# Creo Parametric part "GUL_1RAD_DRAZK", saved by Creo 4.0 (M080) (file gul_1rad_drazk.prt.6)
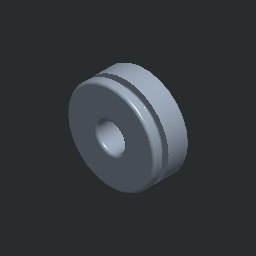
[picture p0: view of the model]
Units: millimeter Kilogram Sec (mmKs); MM, KILOGRAM, SECS
Materials in the file: OCEL_N

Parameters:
  MFG_WP_MATERIAL = "RO5_5"
  NAZOV = "GUL_1RAD_DRAZK"
  PTC_MATERIAL_NAME = "OCEL_N"

Other parameters: HMOTNOST, HUSTOTA

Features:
  1. round
  2. datum plane "DTM2"
  3. cut
  4. round

Named dimensions: velke_D, male_b

Layers: 1, 2, 3, 4, 5, 6, 7, 8, 9, 10, 11, 12, 13, 14, 15, 16, 17, 18, 19, 20, 21, 22, 23, 24, 25, 26, 27, 28, 29, 30, 31, 32

Family table entries: GENERIC, LOZISKO_6203AN, GUL_1RAD_DRAZK, value(d_val), 2/D, 2/(, value(i_val), LOZISKO_6204AN, GUL_1RAD_DRAZK, !/4, 2/,, LOZISKO_6304AN, GUL_1RAD_DRAZK, !/4, 2/J, 2/., LOZISKO_6404N, GUL_1RAD_DRAZK, !/4, 2/R, 2/3, LOZISKO_6205AN, GUL_1RAD_DRAZK, !/9, 2/J, 2/., LOZISKO_6305AN, GUL_1RAD_DRAZK, !/9, 2/O, 2/1, LOZISKO_6405N, GUL_1RAD_DRAZK, !/9, 2/T, 2/5, LOZISKO_6006AN, GUL_1RAD_DRAZK, !/>, 2/*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

Surfaces: 12 torus, 4 plane, 4 cylinder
